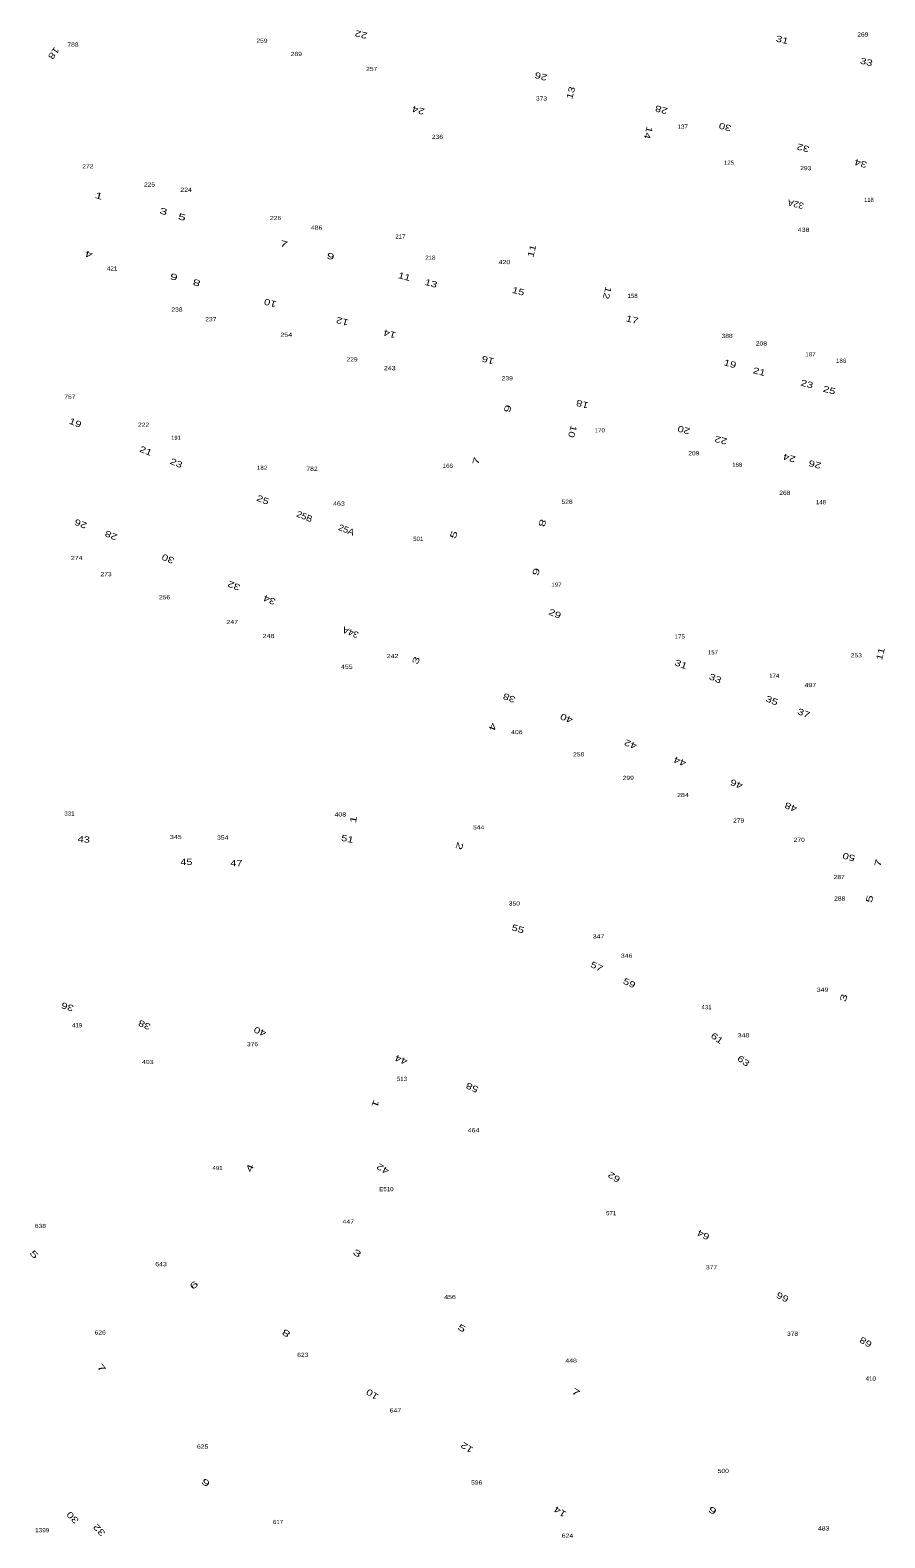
# Model space of a CAD drawing. Extents: x -828673 to -815583, y -1077737 to -1063807.
# Drawn here: x -818529 to -818324.1, y -1069307.9 to -1068946.4 of the extents above; entities that cross this region are included whole.
import ezdxf
from ezdxf.enums import TextEntityAlignment as Align

# ---------------------------------------------------------------- set-up
doc = ezdxf.new("R2010")
doc.units = 0
doc.header["$LTSCALE"] = 0.4
doc.layers.add('1', color=7, linetype='Continuous')
doc.layers.add('2', color=7, linetype='Continuous')

msp = doc.modelspace()

# ---------------------------------------------------------------- texts
at = {"layer": '1'}
for s, width, p in [('788', 1.2, (-818518.729, -1068950.34)), ('259', 1.2, (-818473.433, -1068949.416)), ('269', 1.2, (-818329.403, -1068947.924)), ('289', 1.2, (-818465.19, -1068952.588)), ('257', 1.2, (-818447.118, -1068956.183)), ('373', 1.2, (-818406.43, -1068963.268)), ('137', 1.1, (-818372.57, -1068970.008)), ('236', 1.2, (-818431.371, -1068972.467)), ('125', 1.1, (-818361.499, -1068978.661)), ('272', 1.2, (-818515.178, -1068979.552)), ('293', 1.2, (-818343.075, -1068979.959)), ('225', 1.2, (-818500.382, -1068983.887)), ('224', 1.25, (-818491.61, -1068985.156)), ('226', 1.2, (-818470.157, -1068991.924)), ('486', 1.25, (-818460.328, -1068994.25)), ('217', 1.1, (-818440.248, -1068996.365)), ('438', 1.25, (-818343.594, -1068994.757)), ('421', 1.1, (-818509.34, -1069004.03)), ('218', 1.1, (-818433.062, -1069001.44)), ('420', 1.25, (-818415.307, -1069002.498)), ('158', 1.1, (-818384.593, -1069010.593)), ('238', 1.2, (-818493.805, -1069013.889)), ('237', 1.2, (-818485.69, -1069016.209)), ('254', 1.25, (-818467.605, -1069019.92)), ('388', 1.2, (-818361.931, -1069020.198)), ('208', 1.2, (-818353.714, -1069022.016)), ('229', 1.2, (-818451.838, -1069025.836)), ('187', 1.1, (-818341.951, -1069024.612)), ('186', 1.1, (-818334.599, -1069026.169)), ('243', 1.25, (-818442.795, -1069027.923)), ('239', 1.2, (-818414.624, -1069030.359)), ('757', 1.2, (-818519.462, -1069034.769)), ('222', 1.2, (-818501.805, -1069041.494)), ('170', 1.1, (-818392.441, -1069042.838)), ('182', 1.1, (-818473.401, -1069051.817)), ('166', 1.1, (-818428.883, -1069051.353)), ('209', 1.2, (-818369.912, -1069048.346)), ('168', 1.1, (-818359.513, -1069051.1)), ('782', 1.2, (-818461.426, -1069052.068)), ('268', 1.2, (-818348.095, -1069057.831)), ('463', 1.25, (-818454.968, -1069060.4)), ('528', 1.2, (-818400.291, -1069059.973)), ('148', 1.1, (-818339.43, -1069060.075)), ('501', 1.1, (-818435.955, -1069068.867)), ('274', 1.25, (-818517.817, -1069073.454)), ('273', 1.2, (-818510.803, -1069077.328)), ('197', 1.1, (-818402.84, -1069079.862)), ('256', 1.2, (-818496.775, -1069082.884)), ('247', 1.25, (-818480.554, -1069088.805)), ('248', 1.25, (-818471.86, -1069092.167)), ('175', 1.1, (-818373.276, -1069092.305)), ('242', 1.25, (-818442.107, -1069096.974)), ('157', 1.1, (-818365.324, -1069096.079)), ('253', 1.2, (-818330.969, -1069096.793)), ('455', 1.25, (-818453.082, -1069099.551)), ('174', 1.1, (-818350.644, -1069101.688)), ('497', 1.25, (-818341.979, -1069103.932)), ('406', 1.25, (-818412.334, -1069115.2)), ('258', 1.2, (-818397.516, -1069120.534)), ('299', 1.2, (-818385.632, -1069126.19)), ('284', 1.25, (-818372.526, -1069130.303)), ('331', 1.1, (-818519.574, -1069134.733)), ('408', 1.25, (-818454.625, -1069134.958)), ('544', 1.2, (-818421.487, -1069138.039)), ('279', 1.2, (-818359.164, -1069136.409)), ('345', 1.25, (-818494.074, -1069140.362)), ('354', 1.25, (-818482.822, -1069140.508)), ('270', 1.2, (-818344.646, -1069141.037)), ('287', 1.2, (-818335.074, -1069149.97)), ('350', 1.2, (-818412.929, -1069156.297)), ('288', 1.2, (-818334.945, -1069155.112)), ('347', 1.25, (-818392.758, -1069164.203)), ('346', 1.25, (-818386.012, -1069168.83)), ('349', 1.25, (-818339.052, -1069176.993)), ('431', 1.1, (-818366.858, -1069181.181)), ('419', 1.1, (-818517.732, -1069185.507)), ('348', 1.25, (-818358.003, -1069187.919)), ('376', 1.2, (-818475.68, -1069190.039)), ('403', 1.25, (-818500.791, -1069194.321)), ('513', 1.1, (-818439.87, -1069198.371)), ('464', 1.25, (-818422.703, -1069210.688)), ('491', 1.1, (-818484.076, -1069219.744)), ('E510', 1.1, (-818443.597, -1069224.812)), ('447', 1.25, (-818452.745, -1069232.608)), ('571', 1.1, (-818389.725, -1069230.574)), ('638', 1.2, (-818526.542, -1069233.642)), ('643', 1.25, (-818497.629, -1069242.795)), ('377', 1.2, (-818365.669, -1069243.569)), ('456', 1.25, (-818428.35, -1069250.687)), ('626', 1.2, (-818512.198, -1069259.179)), ('378', 1.2, (-818346.243, -1069259.501)), ('623', 1.2, (-818463.643, -1069264.555)), ('448', 1.25, (-818399.325, -1069265.941)), ('410', 1.1, (-818327.496, -1069270.235)), ('647', 1.25, (-818441.434, -1069277.871)), ('625', 1.2, (-818487.646, -1069286.541)), ('596', 1.2, (-818421.961, -1069295.176)), ('617', 1.1, (-818469.571, -1069304.624)), ('1399', 1.15, (-818526.1, -1069306.601)), ('624', 1.25, (-818400.205, -1069307.921)), ('483', 1.25, (-818338.79, -1069306.167))]:
    msp.add_text(s, height=1, dxfattribs=dict(at, width=width)).set_placement(p, align=Align.CENTER)
for s, p in [('118', (-818327.939, -1068987.575)), ('191', (-818494.037, -1069044.625))]:
    msp.add_text(s, height=1, dxfattribs=at).set_placement(p, align=Align.CENTER)
at = {"layer": '1', "width": 1.2}
msp.add_text('500', height=1, rotation=1.052, dxfattribs=at).set_placement((-818362.8452, -1069292.3815), align=Align.CENTER)
at = {"layer": '2'}
for s, rotation, width, p in [('22', 166.292, 1.35, (-818449.4943, -1068946.708)), ('31', 346.203, 1.35, (-818348.9144, -1068949.4182)), ('18', 235.339, 1.35, (-818523.9675, -1068951.4835)), ('33', 346.163, 1.35, (-818328.7274, -1068954.7113)), ('26', 165.53, 1.35, (-818406.3756, -1068956.7494)), ('13', 75.223, 1.35, (-818398.6946, -1068961.5943)), ('24', 164.516, 1.35, (-818435.7548, -1068964.8875)), ('28', 165.241, 1.35, (-818377.5029, -1068964.747)), ('14', 254.745, 1.35, (-818381.5298, -1068970.7757)), ('30', 164.604, 1.35, (-818362.2164, -1068968.8907)), ('32', 165.157, 1.35, (-818343.5334, -1068973.9119)), ('34', 164.233, 1.35, (-818329.6952, -1068977.6292)), ('1', 344.093, 1.65, (-818512.7236, -1068986.8243)), ('3', 344.831, 1.65, (-818497.2197, -1068990.5557)), ('32A', 165.847, 1.1, (-818345.3241, -1068987.4011)), ('5', 345.192, 1.65, (-818492.7802, -1068991.9268)), ('4', 165.192, 1.65, (-818514.7478, -1068999.3952)), ('7', 344.838, 1.65, (-818468.3677, -1068998.3806)), ('9', 345.57, 1.65, (-818457.1649, -1069001.3348)), ('11', 75.183, 1.35, (-818408.0345, -1068999.5213)), ('6', 165.1, 1.65, (-818494.3442, -1069004.8456)), ('8', 164.922, 1.65, (-818488.8954, -1069006.2368)), ('11', 344.636, 1.35, (-818439.5042, -1069006.1915)), ('13', 344.87, 1.35, (-818433.0898, -1069007.8146)), ('10', 165.243, 1.35, (-818471.243, -1069011.0871)), ('15', 345.227, 1.35, (-818412.1642, -1069009.7133)), ('12', 255.8, 1.35, (-818391.3817, -1069009.198)), ('12', 165.248, 1.35, (-818453.969, -1069015.4952)), ('14', 164.781, 1.35, (-818442.6076, -1069018.5052)), ('17', 346.02, 1.35, (-818384.8622, -1069016.5169)), ('16', 165.24, 1.35, (-818419.0739, -1069024.774)), ('19', 344.368, 1.35, (-818361.4241, -1069027.0893)), ('21', 345.489, 1.35, (-818354.4164, -1069028.9837)), ('23', 345.111, 1.35, (-818342.9857, -1069031.9513)), ('25', 345.111, 1.35, (-818337.6237, -1069033.4223)), ('9', 74.573, 1.65, (-818413.8123, -1069037.361)), ('18', 164.63, 1.35, (-818396.4157, -1069035.3553)), ('19', 338.094, 1.35, (-818518.4458, -1069041.2294)), ('10', 254.985, 1.35, (-818399.7134, -1069042.4282)), ('20', 164.649, 1.35, (-818372.1119, -1069041.5418)), ('21', 338.59, 1.35, (-818501.5388, -1069047.953)), ('22', 166.314, 1.35, (-818363.2416, -1069043.9976)), ('23', 337.745, 1.35, (-818494.2385, -1069050.8803)), ('7', 74.734, 1.65, (-818421.3489, -1069049.8865)), ('24', 164.465, 1.35, (-818346.8286, -1069048.2731)), ('26', 165.579, 1.35, (-818340.7117, -1069049.8087)), ('25', 338.323, 1.35, (-818473.487, -1069059.6927)), ('26', 158.749, 1.35, (-818516.6187, -1069064.068)), ('25B', 338.321, 1.1, (-818463.4761, -1069063.6973)), ('25A', 338.437, 1.1, (-818453.4616, -1069066.8955)), ('8', 254.661, 1.65, (-818406.9324, -1069064.3736)), ('28', 157.813, 1.35, (-818509.3118, -1069066.8405)), ('5', 69.044, 1.65, (-818426.7532, -1069067.6377)), ('30', 157.949, 1.35, (-818495.6704, -1069072.4617)), ('6', 248.381, 1.65, (-818408.4083, -1069075.9942)), ('32', 158.921, 1.35, (-818479.8883, -1069078.8992)), ('34', 157.627, 1.35, (-818471.3395, -1069082.3277)), ('29', 337.694, 1.35, (-818403.4952, -1069087.0065)), ('34A', 157.95, 1.1, (-818451.9129, -1069090.1219)), ('3', 67.76, 1.65, (-818435.8158, -1069097.8194)), ('31', 338.868, 1.35, (-818373.2644, -1069099.1371)), ('11', 75.986, 1.35, (-818324.4601, -1069096.1391)), ('33', 337.554, 1.35, (-818365.0394, -1069102.519)), ('38', 158.995, 1.35, (-818413.9037, -1069105.8351)), ('35', 338.287, 1.35, (-818351.48, -1069107.8197)), ('40', 158.092, 1.35, (-818400.1542, -1069110.7235)), ('37', 338.499, 1.35, (-818343.8354, -1069110.8783)), ('4', 248.176, 1.65, (-818418.7965, -1069113.1732)), ('42', 158.608, 1.35, (-818384.8004, -1069116.9604)), ('44', 157.913, 1.35, (-818372.9805, -1069121.0701)), ('46', 158.227, 1.35, (-818359.4253, -1069126.4699)), ('48', 158.399, 1.35, (-818346.3849, -1069131.9991)), ('1', 78.883, 1.65, (-818450.7664, -1069135.8201)), ('43', 355.855, 1.3, (-818516.1762, -1069141.1843)), ('51', 348.541, 1.35, (-818453.0855, -1069141.0499)), ('2', 252.255, 1.65, (-818426.7768, -1069141.7909)), ('50', 165.591, 1.35, (-818332.5724, -1069143.9251)), ('45', 359.593, 1.3, (-818491.5573, -1069146.5785)), ('47', 358.698, 1.3, (-818479.574, -1069146.8736)), ('7', 77.391, 1.65, (-818325.0214, -1069146.2697)), ('5', 76.719, 1.65, (-818327.0716, -1069154.8823)), ('55', 343.202, 1.35, (-818412.2808, -1069162.6112)), ('57', 333.635, 1.35, (-818393.5261, -1069171.5931)), ('59', 335.194, 1.35, (-818385.6872, -1069175.5704)), ('36', 162.922, 1.35, (-818519.8247, -1069179.8816)), ('3', 75.696, 1.65, (-818333.2912, -1069178.6278)), ('38', 156.522, 1.35, (-818501.2992, -1069184.2545)), ('40', 156.522, 1.35, (-818473.5992, -1069185.8355)), ('61', 324.086, 1.35, (-818364.7924, -1069188.7087)), ('44', 157.982, 1.35, (-818439.7923, -1069192.6167)), ('63', 323.95, 1.35, (-818358.4464, -1069194.1527)), ('58', 156.043, 1.35, (-818422.739, -1069199.2715)), ('1', 248.15, 1.65, (-818446.9078, -1069203.5419)), ('4', 66.935, 1.65, (-818475.6558, -1069219.5563)), ('42', 149.601, 1.35, (-818444.0795, -1069218.7862)), ('62', 148.079, 1.35, (-818388.6394, -1069220.8024)), ('64', 152.868, 1.35, (-818367.2985, -1069234.6145)), ('3', 328.286, 1.7, (-818450.9953, -1069240.3106)), ('5', 311.545, 1.75, (-818528.591, -1069240.4471)), ('6', 41.564, 1.75, (-818489.2461, -1069247.8958)), ('66', 153.801, 1.35, (-818348.3264, -1069249.5341)), ('5', 328.233, 1.7, (-818425.9229, -1069258.2763)), ('8', 147.591, 1.7, (-818467.248, -1069258.2277)), ('68', 149.744, 1.35, (-818328.3326, -1069260.359)), ('7', 311.637, 1.75, (-818512.4397, -1069267.6772)), ('10', 147.29, 1.35, (-818446.5832, -1069272.888)), ('7', 328.507, 1.7, (-818398.5903, -1069273.6415)), ('12', 147.938, 1.35, (-818423.8949, -1069285.6359)), ('9', 319.846, 1.75, (-818487.3996, -1069295.2742)), ('30', 133.5, 1.4, (-818518.2652, -1069302.5583)), ('14', 147.691, 1.35, (-818401.5726, -1069301.0432)), ('9', 328.141, 1.7, (-818365.8389, -1069302.0061)), ('32', 132.738, 1.4, (-818511.8995, -1069305.56))]:
    msp.add_text(s, height=1.5, rotation=rotation, dxfattribs=dict(at, width=width)).set_placement(p, align=Align.CENTER)

doc.saveas('drawing.dxf')
